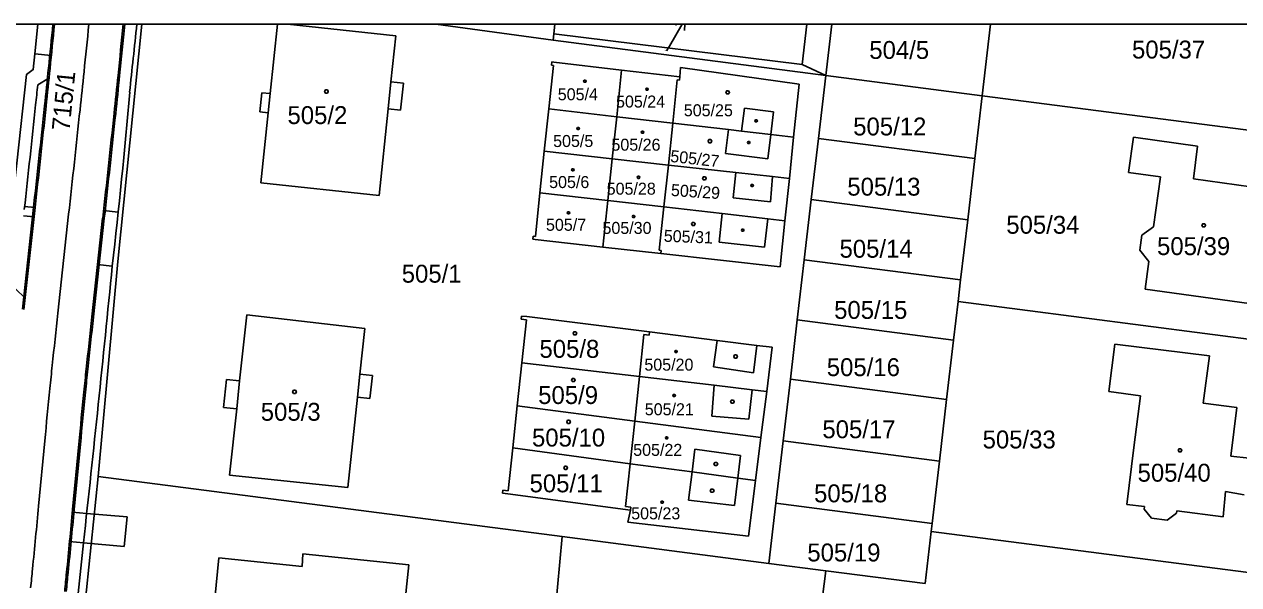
# Model space of a CAD drawing. Extents: x -639590 to -639298, y -1193269 to -1192863.
# Drawn here: x -639511.2 to -639395.8, y -1192916.5 to -1192863.3 of the extents above; entities that cross this region are included whole.
import ezdxf

# ---------------------------------------------------------------- set-up
doc = ezdxf.new("R2010")
doc.units = 0
for name, color, linetype in [('Vrstva 1', 7, 'Continuous'), ('Vrstva 19', 7, 'Continuous'), ('Vrstva 2', 7, 'Continuous'), ('Vrstva 20', 7, 'Continuous'), ('Vrstva 22', 7, 'Continuous'), ('Vrstva 4', 7, 'Continuous'), ('Vrstva 5', 7, 'Continuous'), ('Vrstva 61', 7, 'Continuous'), ('Vrstva 7', 7, 'Continuous')]:
    doc.layers.add(name, color=color, linetype=linetype)

msp = doc.modelspace()

# ---------------------------------------------------------------- linework, layer by layer
at = {"layer": 'Vrstva 1'}
for p, q in [((-639500.02, -1192863.27), (-639502.3, -1192885.82)), ((-639487.11, -1192863.27), (-639487.81, -1192869.85)), ((-639475.88, -1192864.37), (-639486.16, -1192863.27)), ((-639460.93, -1192864.78), (-639472.08, -1192863.27)), ((-639460.84, -1192864.19), (-639460.93, -1192864.78)), ((-639460.75, -1192863.27), (-639460.84, -1192864.19)), ((-639437.25, -1192867.1), (-639460.84, -1192864.19)), ((-639436.82, -1192863.27), (-639437.25, -1192867.1)), ((-639435.01, -1192868.14), (-639434.44, -1192863.27)), ((-639420.13, -1192870.07), (-639419.34, -1192863.27)), ((-639476.34, -1192868.73), (-639475.88, -1192864.37)), ((-639460.93, -1192864.78), (-639435.01, -1192868.14)), ((-639461.33, -1192871.31), (-639460.89, -1192867.17)), ((-639461.09, -1192867.15), (-639461.06, -1192866.85)), ((-639461.09, -1192867.15), (-639460.89, -1192867.17)), ((-639460.86, -1192866.87), (-639461.06, -1192866.85)), ((-639454.41, -1192867.62), (-639460.86, -1192866.87)), ((-639454.41, -1192867.62), (-639454.88, -1192872.05)), ((-639448.89, -1192868.27), (-639454.41, -1192867.62)), ((-639448.83, -1192867.36), (-639448.89, -1192868.27)), ((-639437.53, -1192868.96), (-639448.83, -1192867.36)), ((-639437.25, -1192867.1), (-639435.01, -1192868.14)), ((-639475.15, -1192868.85), (-639476.34, -1192868.73)), ((-639475.42, -1192871.43), (-639475.15, -1192868.85)), ((-639449.55, -1192872.67), (-639449.12, -1192868.55)), ((-639448.92, -1192868.57), (-639449.12, -1192868.55)), ((-639448.92, -1192868.57), (-639448.89, -1192868.27)), ((-639435.71, -1192874.11), (-639435.01, -1192868.14)), ((-639435.01, -1192868.14), (-639420.13, -1192870.07)), ((-639488.6, -1192869.77), (-639488.79, -1192871.6)), ((-639487.81, -1192869.85), (-639488.6, -1192869.77)), ((-639438.06, -1192873.99), (-639437.53, -1192868.96)), ((-639420.13, -1192870.07), (-639420.83, -1192876.03)), ((-639420.13, -1192870.07), (-639385.35, -1192874.56)), ((-639488.79, -1192871.6), (-639488, -1192871.69)), ((-639488, -1192871.69), (-639488.7, -1192878.32)), ((-639477.47, -1192879.53), (-639476.61, -1192871.31)), ((-639476.61, -1192871.31), (-639475.42, -1192871.43)), ((-639461.76, -1192875.34), (-639461.33, -1192871.31)), ((-639461.33, -1192871.31), (-639454.88, -1192872.05)), ((-639454.88, -1192872.05), (-639455.31, -1192876.05)), ((-639454.88, -1192872.05), (-639449.55, -1192872.67)), ((-639449.55, -1192872.67), (-639449.96, -1192876.65)), ((-639449.55, -1192872.67), (-639444.26, -1192873.28)), ((-639444.26, -1192873.28), (-639443.02, -1192873.42)), ((-639443.02, -1192873.42), (-639440.23, -1192873.74)), ((-639440.23, -1192873.74), (-639438.06, -1192873.99)), ((-639438.47, -1192877.92), (-639438.06, -1192873.99)), ((-639436.38, -1192879.92), (-639435.71, -1192874.11)), ((-639435.71, -1192874.11), (-639420.83, -1192876.03)), ((-639405.77, -1192873.99), (-639406.23, -1192877.35)), ((-639399.68, -1192874.84), (-639405.77, -1192873.99)), ((-639462.17, -1192879.28), (-639461.76, -1192875.34)), ((-639455.31, -1192876.05), (-639461.76, -1192875.34)), ((-639400.07, -1192877.95), (-639399.68, -1192874.84)), ((-639455.31, -1192876.05), (-639455.73, -1192880.02)), ((-639449.96, -1192876.65), (-639455.31, -1192876.05)), ((-639449.96, -1192876.65), (-639450.4, -1192880.62)), ((-639443.55, -1192877.36), (-639449.96, -1192876.65)), ((-639420.83, -1192876.03), (-639421.51, -1192881.84)), ((-639440.06, -1192877.74), (-639443.55, -1192877.36)), ((-639438.47, -1192877.92), (-639440.06, -1192877.74)), ((-639438.89, -1192881.94), (-639438.47, -1192877.92)), ((-639406.23, -1192877.35), (-639403.2, -1192877.77)), ((-639403.2, -1192877.77), (-639403.85, -1192882.5)), ((-639393.25, -1192878.92), (-639400.07, -1192877.95)), ((-639488.7, -1192878.32), (-639477.47, -1192879.53)), ((-639462.61, -1192883.42), (-639462.17, -1192879.28)), ((-639462.17, -1192879.28), (-639455.73, -1192880.02)), ((-639455.73, -1192880.02), (-639456.21, -1192884.44)), ((-639455.73, -1192880.02), (-639450.4, -1192880.62)), ((-639437.05, -1192885.64), (-639436.38, -1192879.92)), ((-639436.38, -1192879.92), (-639421.51, -1192881.84)), ((-639450.4, -1192880.62), (-639450.84, -1192884.74)), ((-639450.4, -1192880.62), (-639444.87, -1192881.26)), ((-639444.87, -1192881.26), (-639440.52, -1192881.75)), ((-639440.52, -1192881.75), (-639438.89, -1192881.94)), ((-639439.35, -1192886.33), (-639438.89, -1192881.94)), ((-639421.51, -1192881.84), (-639422.19, -1192887.56)), ((-639403.85, -1192882.5), (-639404.96, -1192883.3)), ((-639462.84, -1192883.7), (-639462.81, -1192883.4)), ((-639462.84, -1192883.7), (-639462.64, -1192883.72)), ((-639462.81, -1192883.4), (-639462.61, -1192883.42)), ((-639456.21, -1192884.44), (-639462.64, -1192883.72)), ((-639404.96, -1192883.3), (-639405.16, -1192884.72)), ((-639450.67, -1192885.06), (-639456.21, -1192884.44)), ((-639450.64, -1192884.76), (-639450.84, -1192884.74)), ((-639450.67, -1192885.06), (-639450.64, -1192884.76)), ((-639405.16, -1192884.72), (-639404.3, -1192885.8)), ((-639502.3, -1192885.82), (-639504.16, -1192906.23)), ((-639439.35, -1192886.33), (-639450.67, -1192885.06)), ((-639437.72, -1192891.36), (-639437.05, -1192885.64)), ((-639437.05, -1192885.64), (-639422.19, -1192887.56)), ((-639404.3, -1192885.8), (-639404.66, -1192888.45)), ((-639422.19, -1192887.56), (-639422.43, -1192889.62)), ((-639404.66, -1192888.45), (-639394.77, -1192889.8)), ((-639422.43, -1192889.62), (-639422.86, -1192893.28)), ((-639422.43, -1192889.62), (-639388.91, -1192893.95)), ((-639490.05, -1192890.89), (-639490.72, -1192897.15)), ((-639478.82, -1192892.16), (-639490.05, -1192890.89)), ((-639463.92, -1192891), (-639463.95, -1192891.3)), ((-639463.95, -1192891.3), (-639463.45, -1192891.35)), ((-639463.42, -1192891.05), (-639463.92, -1192891)), ((-639463.89, -1192895.44), (-639463.45, -1192891.35)), ((-639463.42, -1192891.05), (-639451.76, -1192892.5)), ((-639438.37, -1192897), (-639437.72, -1192891.36)), ((-639437.72, -1192891.36), (-639422.86, -1192893.28)), ((-639479.29, -1192896.52), (-639478.82, -1192892.16)), ((-639452.3, -1192892.75), (-639452.72, -1192896.74)), ((-639452.3, -1192892.75), (-639451.8, -1192892.81)), ((-639451.8, -1192892.81), (-639451.76, -1192892.5)), ((-639451.76, -1192892.5), (-639445.33, -1192893.31)), ((-639445.33, -1192893.31), (-639441.55, -1192893.78)), ((-639441.55, -1192893.78), (-639440.09, -1192893.96)), ((-639440.09, -1192893.96), (-639440.62, -1192898.15)), ((-639422.86, -1192893.28), (-639423.52, -1192898.92)), ((-639408.11, -1192898.17), (-639407.53, -1192893.65)), ((-639407.53, -1192893.65), (-639398.54, -1192894.78)), ((-639398.54, -1192894.78), (-639399.12, -1192899.27)), ((-639478.1, -1192896.65), (-639479.29, -1192896.52)), ((-639464.33, -1192899.52), (-639463.89, -1192895.44)), ((-639452.72, -1192896.74), (-639463.89, -1192895.44)), ((-639491.97, -1192897.02), (-639492.25, -1192899.67)), ((-639490.72, -1192897.15), (-639491.97, -1192897.02)), ((-639478.33, -1192898.83), (-639478.1, -1192896.65)), ((-639452.72, -1192896.74), (-639453.17, -1192900.97)), ((-639445.63, -1192897.57), (-639452.72, -1192896.74)), ((-639442, -1192897.99), (-639445.63, -1192897.57)), ((-639439.05, -1192902.85), (-639438.37, -1192897)), ((-639438.37, -1192897), (-639423.52, -1192898.92)), ((-639480.44, -1192907.28), (-639479.52, -1192898.7)), ((-639479.52, -1192898.7), (-639478.33, -1192898.83)), ((-639440.62, -1192898.15), (-639442, -1192897.99)), ((-639440.62, -1192898.15), (-639441.17, -1192902.54)), ((-639405.08, -1192898.56), (-639408.11, -1192898.17)), ((-639405.71, -1192903.49), (-639405.08, -1192898.56)), ((-639492.25, -1192899.67), (-639491, -1192899.81)), ((-639491, -1192899.81), (-639491.67, -1192906.12)), ((-639464.75, -1192903.51), (-639464.33, -1192899.52)), ((-639453.17, -1192900.97), (-639464.33, -1192899.52)), ((-639423.52, -1192898.92), (-639424.21, -1192904.77)), ((-639399.12, -1192899.27), (-639395.93, -1192899.67)), ((-639395.93, -1192899.67), (-639396.51, -1192904.3)), ((-639453.17, -1192900.97), (-639453.6, -1192905.02)), ((-639441.17, -1192902.54), (-639453.17, -1192900.97)), ((-639441.17, -1192902.54), (-639441.69, -1192906.63)), ((-639439.74, -1192908.77), (-639439.05, -1192902.85)), ((-639439.05, -1192902.85), (-639424.21, -1192904.77)), ((-639465.19, -1192907.6), (-639464.75, -1192903.51)), ((-639453.6, -1192905.02), (-639464.75, -1192903.51)), ((-639406.4, -1192908.89), (-639405.71, -1192903.49)), ((-639396.51, -1192904.3), (-639394.77, -1192904.49)), ((-639453.6, -1192905.02), (-639454.04, -1192909.09)), ((-639447.72, -1192905.81), (-639453.6, -1192905.02)), ((-639424.21, -1192904.77), (-639424.9, -1192910.69)), ((-639504.16, -1192906.23), (-639505.82, -1192922.39)), ((-639504.16, -1192906.23), (-639460.05, -1192911.94)), ((-639491.67, -1192906.12), (-639480.44, -1192907.28)), ((-639443.36, -1192906.4), (-639447.72, -1192905.81)), ((-639441.69, -1192906.63), (-639443.36, -1192906.4)), ((-639441.69, -1192906.63), (-639442.36, -1192911.91)), ((-639465.69, -1192907.55), (-639465.72, -1192907.83)), ((-639465.72, -1192907.83), (-639465.22, -1192907.9)), ((-639465.69, -1192907.55), (-639465.19, -1192907.6)), ((-639453.58, -1192909.45), (-639465.22, -1192907.9)), ((-639397, -1192907.67), (-639397.25, -1192910.06)), ((-639395.23, -1192907.97), (-639397, -1192907.67)), ((-639454.04, -1192909.09), (-639453.54, -1192909.15)), ((-639453.54, -1192909.15), (-639453.58, -1192909.45)), ((-639440.41, -1192914.49), (-639439.74, -1192908.77)), ((-639439.74, -1192908.77), (-639424.9, -1192910.69)), ((-639404.71, -1192909.1), (-639406.4, -1192908.89)), ((-639404.74, -1192909.33), (-639404.71, -1192909.1)), ((-639453.83, -1192910.59), (-639453.58, -1192909.45)), ((-639404.04, -1192910.2), (-639404.74, -1192909.33)), ((-639402.55, -1192910.39), (-639404.04, -1192910.2)), ((-639401.66, -1192909.73), (-639402.55, -1192910.39)), ((-639401.63, -1192909.5), (-639401.66, -1192909.73)), ((-639397.25, -1192910.06), (-639401.63, -1192909.5)), ((-639442.36, -1192911.91), (-639453.83, -1192910.59)), ((-639424.99, -1192911.45), (-639425.57, -1192916.41)), ((-639424.9, -1192910.69), (-639424.99, -1192911.45)), ((-639391.47, -1192915.8), (-639424.99, -1192911.45)), ((-639461.52, -1192927.91), (-639460.05, -1192911.94)), ((-639460.05, -1192911.94), (-639440.41, -1192914.49)), ((-639484.79, -1192914.79), (-639484.7, -1192913.59)), ((-639474.65, -1192914.63), (-639484.7, -1192913.59)), ((-639492.68, -1192913.98), (-639493.6, -1192922.99)), ((-639484.79, -1192914.79), (-639492.68, -1192913.98)), ((-639475.12, -1192919.21), (-639474.65, -1192914.63)), ((-639440.41, -1192914.49), (-639434.99, -1192915.19)), ((-639434.99, -1192915.19), (-639437.01, -1192931.02)), ((-639434.99, -1192915.19), (-639425.57, -1192916.41))]:
    msp.add_line(p, q, dxfattribs=at)
at = {"layer": 'Vrstva 19'}
for p, q in [((-639510.2, -1192880.97), (-639511.23, -1192890.36)), ((-639503.74, -1192881.68), (-639504.76, -1192891.07)), ((-639506, -1192903.16), (-639506.59, -1192909.36))]:
    msp.add_line(p, q, dxfattribs=at)
for points in [[(-639506.97, -1192881.32), (-639508, -1192890.71)], [(-639509.24, -1192902.85), (-639509.83, -1192909.06)]]:
    msp.add_lwpolyline(points, dxfattribs=at)
for centre, radius, start, end in [((-642489.65, -1192559.73), 2996.75, 354.10607, 354.18658), ((-642489.65, -1192559.73), 3000, 354.10607, 354.1929), ((-642489.65, -1192559.73), 3003.25, 354.10607, 354.19921), ((-640997.53, -1192712.93), 1496.79, 353.93638, 354.07424), ((-640997.53, -1192712.93), 1500.04, 353.93638, 354.07424), ((-640997.53, -1192712.93), 1503.29, 353.93638, 354.07424), ((-642488.93, -1192552.83), 2996.76, 353.71357, 353.90455), ((-642488.93, -1192552.83), 3000, 353.71357, 353.90455), ((-642488.93, -1192552.83), 3003.26, 353.71357, 353.90455), ((-638527.12, -1192999.08), 986.84, 173.69574, 173.98604), ((-638527.12, -1192999.08), 983.59, 173.69574, 173.98604), ((-639011.24, -1192947.67), 500, 174.0319, 174.2845), ((-639011.24, -1192947.67), 496.75, 174.0319, 174.2845), ((-638472.17, -1193000.65), 1041.67, 174.33796, 174.61298), ((-638472.17, -1193000.65), 1038.42, 174.33796, 174.61298), ((-641502.93, -1192720.63), 2001.99, 354.42777, 354.59951), ((-641501.16, -1192720.81), 2003.46, 354.42773, 354.59962), ((-640505.63, -1192817.43), 1000, 354.29543, 354.39908), ((-640505.63, -1192817.43), 1003.25, 354.29543, 354.39908)]:
    msp.add_arc(centre, radius, start, end, dxfattribs=at)
at = {"layer": 'Vrstva 20'}
for p, q in [((-639510.19, -1192866.08), (-639508.62, -1192866.24)), ((-639509.91, -1192869.03), (-639508.84, -1192868.38)), ((-639510.35, -1192880.95), (-639511.37, -1192890.34)), ((-639511.26, -1192881.47), (-639510.26, -1192881.57)), ((-639511.16, -1192880.58), (-639510.17, -1192880.69)), ((-639502.26, -1192881.12), (-639503.66, -1192880.97)), ((-639503.59, -1192881.69), (-639504.62, -1192891.08)), ((-639502.82, -1192886.24), (-639504.22, -1192886.09)), ((-639512.02, -1192888.41), (-639511.11, -1192889.29)), ((-639505.85, -1192903.18), (-639506.44, -1192909.38)), ((-639506.88, -1192925.23), (-639505.56, -1192912.55))]:
    msp.add_line(p, q, dxfattribs=at)
for points in [[(-639509.9, -1192863.27), (-639510.19, -1192866.08), (-639510.33, -1192867.57), (-639510.97, -1192868.03), (-639511.91, -1192876.46), (-639512.33, -1192880.5), (-639512.79, -1192885.74)], [(-639505.26, -1192909.75), (-639506.62, -1192909.62)], [(-639505.56, -1192912.55), (-639506.88, -1192912.42)]]:
    msp.add_lwpolyline(points, dxfattribs=at)
for centre, radius, start, end in [((-642489.65, -1192559.73), 2996.6, 354.10607, 354.18629), ((-642489.65, -1192559.73), 3003.4, 354.10607, 354.1995), ((-641310.47, -1192674.16), 1819.83, 353.83099, 354.0352), ((-640997.53, -1192712.93), 1496.64, 353.93638, 354.07424), ((-640997.53, -1192712.93), 1503.44, 353.93638, 354.07424), ((-640997.53, -1192712.93), 1495.79, 353.93638, 354.0097), ((-640075.66, -1192820.68), 576.58, 353.47136, 355.12119), ((-642488.93, -1192552.83), 2995.76, 353.71357, 353.90455), ((-642488.93, -1192552.83), 2996.61, 353.71357, 353.90455), ((-642488.93, -1192552.83), 3003.41, 353.71357, 353.90455), ((-642380.95, -1192599.8), 2892.35, 353.79248, 354.31649), ((-638527.12, -1192999.08), 983.44, 173.69574, 173.98604), ((-639011.24, -1192947.67), 496.6, 174.0319, 174.2845), ((-638472.17, -1193000.65), 1038.27, 174.33796, 174.61298), ((-641501.16, -1192720.81), 2003.61, 354.42773, 354.59962), ((-640505.63, -1192817.43), 1003.4, 354.29543, 354.39908)]:
    msp.add_arc(centre, radius, start, end, dxfattribs=at)
at = {"layer": 'Vrstva 22'}
for p, q in [((-639501.4, -1192910.06), (-639505.26, -1192909.75)), ((-639501.68, -1192912.88), (-639501.4, -1192910.06)), ((-639505.56, -1192912.55), (-639501.68, -1192912.88))]:
    msp.add_line(p, q, dxfattribs=at)
at = {"layer": 'Vrstva 4'}
for p, q in [((-639476.34, -1192868.73), (-639476.61, -1192871.31)), ((-639488, -1192871.69), (-639487.81, -1192869.85)), ((-639442.74, -1192871.25), (-639443.02, -1192873.42)), ((-639439.96, -1192871.59), (-639442.74, -1192871.25)), ((-639440.23, -1192873.74), (-639439.96, -1192871.59)), ((-639444.26, -1192873.28), (-639444.55, -1192875.56)), ((-639440.51, -1192876.06), (-639440.23, -1192873.74)), ((-639444.55, -1192875.56), (-639440.51, -1192876.06)), ((-639443.55, -1192877.36), (-639443.8, -1192879.75)), ((-639440.25, -1192880.15), (-639440.06, -1192877.74)), ((-639443.8, -1192879.75), (-639440.25, -1192880.15)), ((-639444.87, -1192881.26), (-639445.13, -1192883.97)), ((-639440.82, -1192884.44), (-639440.52, -1192881.75)), ((-639445.13, -1192883.97), (-639440.82, -1192884.44)), ((-639445.33, -1192893.31), (-639445.69, -1192895.83)), ((-639441.88, -1192896.38), (-639441.55, -1192893.78)), ((-639479.29, -1192896.52), (-639479.52, -1192898.7)), ((-639441.88, -1192896.38), (-639445.69, -1192895.83)), ((-639491, -1192899.81), (-639490.72, -1192897.15)), ((-639445.85, -1192900.51), (-639445.63, -1192897.57)), ((-639442.33, -1192900.78), (-639442, -1192897.99)), ((-639442.33, -1192900.78), (-639445.85, -1192900.51)), ((-639447.44, -1192903.64), (-639447.72, -1192905.81)), ((-639443.1, -1192904.23), (-639447.44, -1192903.64)), ((-639443.36, -1192906.4), (-639443.1, -1192904.23)), ((-639447.72, -1192905.81), (-639448.07, -1192908.49)), ((-639443.68, -1192909), (-639443.36, -1192906.4)), ((-639448.07, -1192908.49), (-639443.68, -1192909))]:
    msp.add_line(p, q, dxfattribs=at)
at = {"layer": 'Vrstva 5'}
for points in [[(-639457.84, -1192868.58), (-639457.78, -1192868.68), (-639457.84, -1192868.78), (-639457.96, -1192868.78), (-639458.02, -1192868.68), (-639457.96, -1192868.58)], [(-639482.38, -1192869.5), (-639482.29, -1192869.65), (-639482.38, -1192869.8), (-639482.56, -1192869.8), (-639482.65, -1192869.65), (-639482.56, -1192869.5)], [(-639451.94, -1192869.34), (-639451.88, -1192869.44), (-639451.94, -1192869.54), (-639452.06, -1192869.54), (-639452.12, -1192869.44), (-639452.06, -1192869.34)], [(-639444.24, -1192869.59), (-639444.15, -1192869.74), (-639444.24, -1192869.89), (-639444.42, -1192869.89), (-639444.51, -1192869.74), (-639444.42, -1192869.59)], [(-639458.48, -1192873.08), (-639458.42, -1192873.18), (-639458.48, -1192873.28), (-639458.6, -1192873.28), (-639458.66, -1192873.18), (-639458.6, -1192873.08)], [(-639452.36, -1192873.43), (-639452.3, -1192873.53), (-639452.36, -1192873.63), (-639452.48, -1192873.63), (-639452.54, -1192873.53), (-639452.48, -1192873.43)], [(-639441.57, -1192872.35), (-639441.51, -1192872.45), (-639441.57, -1192872.55), (-639441.69, -1192872.55), (-639441.75, -1192872.45), (-639441.69, -1192872.35)], [(-639445.93, -1192874.23), (-639445.84, -1192874.38), (-639445.93, -1192874.53), (-639446.11, -1192874.53), (-639446.2, -1192874.38), (-639446.11, -1192874.23)], [(-639442.27, -1192874.41), (-639442.21, -1192874.51), (-639442.27, -1192874.61), (-639442.39, -1192874.61), (-639442.45, -1192874.51), (-639442.39, -1192874.41)], [(-639458.99, -1192876.99), (-639458.93, -1192877.09), (-639458.99, -1192877.19), (-639459.11, -1192877.19), (-639459.17, -1192877.09), (-639459.11, -1192876.99)], [(-639452.74, -1192877.71), (-639452.68, -1192877.81), (-639452.74, -1192877.91), (-639452.86, -1192877.91), (-639452.92, -1192877.81), (-639452.86, -1192877.71)], [(-639446.45, -1192877.76), (-639446.36, -1192877.91), (-639446.45, -1192878.06), (-639446.63, -1192878.06), (-639446.72, -1192877.91), (-639446.63, -1192877.76)], [(-639441.95, -1192878.48), (-639441.89, -1192878.58), (-639441.95, -1192878.68), (-639442.07, -1192878.68), (-639442.13, -1192878.58), (-639442.07, -1192878.48)], [(-639459.4, -1192881.08), (-639459.34, -1192881.18), (-639459.4, -1192881.28), (-639459.52, -1192881.28), (-639459.58, -1192881.18), (-639459.52, -1192881.08)], [(-639453.21, -1192881.43), (-639453.15, -1192881.53), (-639453.21, -1192881.63), (-639453.33, -1192881.63), (-639453.39, -1192881.53), (-639453.33, -1192881.43)], [(-639447.5, -1192882.09), (-639447.41, -1192882.24), (-639447.5, -1192882.39), (-639447.68, -1192882.39), (-639447.77, -1192882.24), (-639447.68, -1192882.09)], [(-639398.99, -1192882.23), (-639398.9, -1192882.38), (-639398.99, -1192882.53), (-639399.17, -1192882.53), (-639399.26, -1192882.38), (-639399.17, -1192882.23)], [(-639442.84, -1192882.73), (-639442.78, -1192882.83), (-639442.84, -1192882.93), (-639442.96, -1192882.93), (-639443.02, -1192882.83), (-639442.96, -1192882.73)], [(-639458.76, -1192892.48), (-639458.67, -1192892.63), (-639458.76, -1192892.78), (-639458.94, -1192892.78), (-639459.03, -1192892.63), (-639458.94, -1192892.48)], [(-639449.18, -1192894.27), (-639449.12, -1192894.37), (-639449.18, -1192894.47), (-639449.3, -1192894.47), (-639449.36, -1192894.37), (-639449.3, -1192894.27)], [(-639443.49, -1192894.68), (-639443.4, -1192894.83), (-639443.49, -1192894.98), (-639443.67, -1192894.98), (-639443.76, -1192894.83), (-639443.67, -1192894.68)], [(-639458.91, -1192896.92), (-639458.82, -1192897.07), (-639458.91, -1192897.22), (-639459.09, -1192897.22), (-639459.18, -1192897.07), (-639459.09, -1192896.92)], [(-639485.41, -1192898.04), (-639485.32, -1192898.19), (-639485.41, -1192898.34), (-639485.59, -1192898.34), (-639485.68, -1192898.19), (-639485.59, -1192898.04)], [(-639449.36, -1192898.44), (-639449.3, -1192898.54), (-639449.36, -1192898.64), (-639449.48, -1192898.64), (-639449.54, -1192898.54), (-639449.48, -1192898.44)], [(-639443.79, -1192898.97), (-639443.7, -1192899.12), (-639443.79, -1192899.27), (-639443.97, -1192899.27), (-639444.06, -1192899.12), (-639443.97, -1192898.97)], [(-639459.36, -1192900.89), (-639459.27, -1192901.04), (-639459.36, -1192901.19), (-639459.54, -1192901.19), (-639459.63, -1192901.04), (-639459.54, -1192900.89)], [(-639450.07, -1192902.47), (-639450.01, -1192902.57), (-639450.07, -1192902.67), (-639450.19, -1192902.67), (-639450.25, -1192902.57), (-639450.19, -1192902.47)], [(-639401.25, -1192903.6), (-639401.16, -1192903.75), (-639401.25, -1192903.9), (-639401.43, -1192903.9), (-639401.52, -1192903.75), (-639401.43, -1192903.6)], [(-639459.64, -1192905.27), (-639459.55, -1192905.42), (-639459.64, -1192905.57), (-639459.82, -1192905.57), (-639459.91, -1192905.42), (-639459.82, -1192905.27)], [(-639445.37, -1192904.9), (-639445.28, -1192905.05), (-639445.37, -1192905.2), (-639445.55, -1192905.2), (-639445.64, -1192905.05), (-639445.55, -1192904.9)], [(-639445.72, -1192907.44), (-639445.63, -1192907.59), (-639445.72, -1192907.74), (-639445.9, -1192907.74), (-639445.99, -1192907.59), (-639445.9, -1192907.44)], [(-639450.5, -1192908.58), (-639450.44, -1192908.68), (-639450.5, -1192908.78), (-639450.62, -1192908.78), (-639450.68, -1192908.68), (-639450.62, -1192908.58)]]:
    msp.add_lwpolyline(points, close=True, dxfattribs=at)
at = {"layer": 'Vrstva 61'}
msp.add_lwpolyline([(-639590.39, -1192863.27), (-639298.39, -1192863.27)], dxfattribs=at)
at = {"layer": 'Vrstva 7'}
for p in [(-639448.67, -1192863.27), (-639450.13, -1192865.8)]:
    msp.add_line(p, (-639449.87, -1192865.34), dxfattribs=at)
for points in [[(-639449.3, -1192863.36), (-639449.16, -1192863.27)], [(-639448.4, -1192863.27), (-639448.43, -1192863.86)]]:
    msp.add_lwpolyline(points, dxfattribs=at)

# ---------------------------------------------------------------- texts
at = {"layer": 'Vrstva 2'}
for s, height, p in [('504/5', 1.7, (-639430.87, -1192866.56)), ('505/37', 1.7, (-639405.9, -1192866.52)), ('504/8', 0.1, (-639450.34, -1192865.8)), ('505/4', 1.14, (-639460.48, -1192870.49)), ('505/24', 1.14, (-639454.94, -1192871.18)), ('505/2', 1.7, (-639486.17, -1192872.75)), ('505/25', 1.14, (-639448.5, -1192872.01)), ('505/12', 1.7, (-639432.4, -1192873.83)), ('505/5', 1.14, (-639460.92, -1192874.93)), ('505/26', 1.14, (-639455.38, -1192875.28)), ('505/6', 1.14, (-639461.3, -1192878.83)), ('505/13', 1.7, (-639432.96, -1192879.55)), ('505/28', 1.14, (-639455.83, -1192879.46)), ('505/34', 1.7, (-639417.85, -1192883.17)), ('505/7', 1.14, (-639461.6, -1192882.89)), ('505/30', 1.14, (-639456.23, -1192883.19)), ('505/14', 1.7, (-639433.7, -1192885.45)), ('505/39', 1.7, (-639403.52, -1192885.2)), ('505/1', 1.7, (-639475.31, -1192887.82)), ('505/15', 1.7, (-639434.21, -1192891.26)), ('505/8', 1.7, (-639462.22, -1192894.96)), ('505/20', 1.14, (-639452.25, -1192896.18)), ('505/16', 1.7, (-639434.91, -1192896.7)), ('505/9', 1.7, (-639462.34, -1192899.35)), ('505/3', 1.7, (-639488.71, -1192900.94)), ('505/21', 1.14, (-639452.21, -1192900.42)), ('505/17', 1.7, (-639435.33, -1192902.6)), ('505/10', 1.7, (-639462.93, -1192903.39)), ('505/33', 1.7, (-639420.1, -1192903.57)), ('505/22', 1.14, (-639453.31, -1192904.28)), ('505/40', 1.7, (-639405.37, -1192906.73)), ('505/11', 1.7, (-639463.16, -1192907.74)), ('505/18', 1.7, (-639436.12, -1192908.69)), ('505/23', 1.14, (-639453.5, -1192910.31)), ('505/19', 1.7, (-639436.76, -1192914.31))]:
    msp.add_text(s, height=height, dxfattribs=at).set_placement(p)
for s, height, rotation, p in [('715/1', 1.7, 84.2894, (-639506.89, -1192873.46)), ('505/27', 1.14, 353.6296, (-639449.83, -1192876.34)), ('505/29', 1.14, 356.3225, (-639449.75, -1192879.58)), ('505/31', 1.14, 357.8121, (-639450.42, -1192883.93))]:
    msp.add_text(s, height=height, rotation=rotation, dxfattribs=at).set_placement(p)

doc.saveas('drawing.dxf')
